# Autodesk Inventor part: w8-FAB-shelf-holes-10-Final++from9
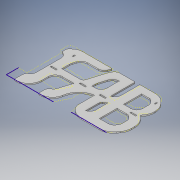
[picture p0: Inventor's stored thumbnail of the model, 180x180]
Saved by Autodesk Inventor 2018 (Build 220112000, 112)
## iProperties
Created: 2018-03
Part Number: w8-FAB-shelf-holes-10-Final++from9
Material: Generic
Document SubType Name: Modeling
Designer: katin
Density: 1 g/cm^3
Appearance: Default
Mass: 2764.59 g
Surface Area: 5789.53 cm^2
Volume: 2764.59 cm^3
Author: katin
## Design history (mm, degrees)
sketch "Sketch1"
  geometry: L1 (0, -103.188)-(-76.2, -103.188); L2 (-382.588, -407.987)-(-201.613, -407.987); L3 (-201.613, -407.987)-(-179.387, -330.2); L4 (-179.387, -330.2)-(-179.387, -303.315); L5 (-179.387, -303.315)-(-382.588, -303.315); L6 (-382.588, -303.315)-(-382.588, -330.2); L7 (-382.588, -330.2)-(-404.813, -407.987); L8 (-404.813, -407.987)-(-446.104, -500); L9 (-914.4, -410.18)-(-914.4, -330.2); L10 (-914.4, -330.2)-(-863.6, -279.4); L11 (-863.6, -279.4)-(-941.188, -201.812); L12 (-941.188, -100.013)-(-863.6, 0); L13 (-611.188, -500)-(-611.188, -274.637); L14 (-660.987, -274.638)-(-660.987, -501.799); L15 (-660.987, -203.2)-(-660.987, -104.775); L16 (-611.188, -104.775)-(-660.987, -104.775); L17 (-458.721, -302.879)-(-458.721, -330.2); L18 (-458.721, -330.2)-(-480.946, -407.987); L19 (-480.946, -407.987)-(-534.987, -407.987); L20 (-534.987, -407.987)-(-534.988, -302.879); L21 (-534.988, -302.879)-(-458.721, -302.879); L22 (-180.346, -201.117)-(-180.346, -104.775); L23 (-180.346, -104.775)-(-330, -104.775); L24 (-180.346, -201.117)-(-380.371, -201.117); L25 (-380.371, -201.117)-(-330, -104.775); L26 (-458.721, -201.117)-(-458.721, -104.775); L27 (-458.721, -201.117)-(-534.987, -201.117); L28 (-534.987, -201.117)-(-534.987, -104.775); L29 (-739.719, -407.987)-(-739.719, -306.388); L30 (-739.719, -407.987)-(-815.975, -407.987); L31 (-841.375, -354.012)-(-841.375, -381); L32 (-841.375, -381)-(-815.975, -407.987); L33 (-382.588, -407.987)-(-424.795, -502.08); L34 (-79.965, -502.08)-(-424.795, -502.08); L35 (-611.188, -104.775)-(-611.188, -203.2); L36 (-611.188, -500)-(-446.104, -500); L37 (0, -103.188)-(0, 0); L38 (-941.188, -201.812)-(-941.188, -100.013); L39 (0, -103.188)-(0, 0); L40 (0, 0)-(-406.4, 0); L41 (-406.4, 0)-(-458.721, -104.775); L42 (-534.987, -104.775)-(-558.8, 0); L43 (-611.188, -203.2)-(-660.987, -233.363); L44 (-660.987, -233.363)-(-660.987, -203.2); L45 (-558.8, 0)-(-863.6, 0); L46 (0, 0)-(-406.4, 0); L47 (-79.965, -502.08)-(-50.58, -485.849); L48 (-50.58, -485.849)-(-50.58, -407.987); L49 (-50.58, -407.987)-(-76.2, -407.987); L50 (-76.2, -407.987)-(-76.2, -103.188); L51 (-841.375, -354.012)-(-793.75, -306.388); L52 (-793.75, -306.388)-(-739.719, -306.388); L53 (-611.188, -274.637)-(-660.987, -274.638); L54 (-739.762, -201.612)-(-739.762, -103.187); L55 (-739.762, -103.187)-(-836.612, -103.188); L56 (-836.612, -103.188)-(-863.6, -138.112); L57 (-863.6, -138.112)-(-863.6, -176.213); L58 (-863.6, -176.213)-(-838.2, -201.612); L59 (-838.2, -201.612)-(-739.762, -201.612); L60 (-914.4, -410.18)-(-838.2, -501.799); L61 (-838.2, -501.799)-(-660.987, -501.799); L62 (0, 0)-(-406.4, 0); L63 (-558.8, 0)-(-863.6, 0)
  constraints: 126 end point, 13 perpendicular, 13 point on line, 10 vertical, 9 horizontal, 3 collinear, 1 parallel
sketch "Sketch2"
  geometry: L1 (0, 0)-(-940, 0); L2 (-940, 0)-(-940, -500); L3 (-940, -500)-(0, -500); L4 (0, -500)-(0, 0)
  constraints: 8 end point, 2 parallel, 1 horizontal, 1 perpendicular
  dimensions: "d10" = 940 distance of L3.end L2.end; "d11" = 500 distance of L2.end L1.end
extrude "Extrusion2" new body sketch "Sketch2" distance "d12" = 11; taper "d13" = 0 deg
sketch "Sketch3"
  geometry: L1 (0, 0)-(0, 500) reference; L2 (0, 408.758)-(113.674, 408.758); L3 (113.674, 408.758)-(113.674, 94.825); L4 (113.674, 94.825)-(0, 94.825); L5 (0, 94.825)-(0, 408.758); L6 (611.188, 500.062)-(650.182, 500.062); L7 (650.182, 500.062)-(650.182, 287.702); L8 (650.182, 287.702)-(611.188, 287.702); L9 (611.188, 287.702)-(611.188, 500.062); L10 (0, 500)-(129.919, 500); L11 (0, 500)-(940, 500) reference; L12 (129.919, 500)-(0, 408.758); L13 (0, 500)-(0, 408.758); L14 (739.775, 406.4)-(739.775, 307.975); L15 (739.775, 307.975)-(793.75, 307.975); L16 (793.75, 307.975)-(836.612, 350.838); L17 (836.612, 350.838)-(841.375, 355.6); L18 (841.375, 355.6)-(841.375, 381); L19 (841.375, 381)-(806.218, 418.355); L20 (806.218, 418.355)-(739.775, 418.355); L21 (739.775, 418.355)-(739.775, 406.4)
  constraints: 38 end point, 6 parallel, 4 perpendicular, 4 point on line, 2 horizontal, 1 collinear, 1 vertical
extrude "Extrusion3" cut sketch "Sketch3" distance "d14" = 150; taper "d15" = 0 deg
sketch "Sketch4"
  geometry: L1 (0, 500)-(940, 500) reference; L2 (839.788, 500)-(914.4, 411.163); L3 (914.4, 411.163)-(914.4, 310.193); L4 (914.4, 310.193)-(880.473, 275.82); L5 (880.473, 275.82)-(940, 217.064); L6 (940, 217.064)-(940, 500); L7 (940, 500)-(839.788, 500); L8 (940, 0)-(940, 500) reference; L9 (940, 99.14)-(940, 0); L10 (940, 0)-(863.6, 0); L11 (0, 0)-(940, 0) reference; L12 (940, 99.14)-(863.6, 0); L13 (728.744, 226.212)-(728.744, 72.721); L14 (728.744, 72.721)-(830.691, 72.721); L15 (830.691, 72.721)-(864.394, 116.456); L16 (864.394, 116.456)-(864.405, 192.017); L17 (864.405, 192.017)-(829.761, 226.212); L18 (829.761, 226.212)-(728.744, 226.212); L19 (649.575, 72.721)-(649.575, 226.081); L20 (649.575, 226.081)-(611.188, 202.869); L21 (611.188, 202.869)-(611.188, 72.721); L22 (611.188, 72.721)-(649.575, 72.721); L23 (727.378, 439.44)-(727.378, 283.141); L24 (727.378, 283.141)-(801.955, 283.141); L25 (801.955, 283.141)-(841.375, 322.561); L26 (841.375, 322.561)-(841.375, 403.65); L27 (841.375, 403.65)-(807.69, 439.44); L28 (807.69, 439.44)-(727.378, 439.44); L29 (534.987, 283.141)-(534.987, 439.44); L30 (534.987, 439.44)-(490.381, 439.44); L31 (490.381, 439.44)-(455.193, 321.307); L32 (455.193, 321.307)-(455.193, 283.141); L33 (455.193, 283.141)-(534.987, 283.141); L34 (534.987, 226.027)-(534.987, 72.721); L35 (534.987, 72.721)-(560.388, 0); L36 (560.388, 0)-(405.603, 0); L37 (455.193, 72.721)-(405.603, 0); L38 (455.193, 72.721)-(455.193, 226.027); L39 (455.193, 226.027)-(534.987, 226.027); L40 (250.031, 72.721)-(195.665, 72.721); L41 (195.665, 72.721)-(195.665, 226.027); L42 (195.665, 226.027)-(354.575, 226.027); L43 (354.575, 226.027)-(250.031, 72.721); L44 (195.665, 283.141)-(195.665, 362.436); L45 (195.665, 362.436)-(218.603, 439.44); L46 (218.603, 439.44)-(389.781, 439.44); L47 (389.781, 439.44)-(415.52, 500); L48 (415.52, 500)-(447.675, 500); L49 (611.188, 500)-(129.919, 500) reference; L50 (195.665, 283.141)-(380.412, 283.141); L51 (380.412, 283.141)-(380.412, 300.037); L52 (380.412, 300.037)-(421.936, 439.44); L53 (421.936, 439.44)-(447.675, 500); L54 (415.52, 500)-(447.675, 500); 1 further point
  constraints: 100 end point, 28 point on line, 12 perpendicular, 11 parallel, 3 vertical, 2 collinear
extrude "Extrusion4" cut sketch "Sketch4" distance "d16" = 150; taper "d17" = 0 deg
fillet "Fillet1" dims "d18" = 50
fillet "Fillet2" dims "d19" = 50
fillet "Fillet3" dims "d20" = 50
fillet "Fillet4" dims "d21" = 60
fillet "Fillet7" dims "d24" = 30
fillet "Fillet8" dims "d25" = 50
fillet "Fillet9" dims "d26" = 50
fillet "Fillet10" dims "d27" = 50
fillet "Fillet13" dims "d30" = 40
fillet "Fillet14" dims "d31" = 120
fillet "Fillet15" dims "d32" = 120
fillet "Fillet16" dims "d33" = 120
fillet "Fillet17" dims "d34" = 50
fillet "Fillet18" dims "d35" = 50
fillet "Fillet19" dims "d36" = 170
fillet "Fillet20" dims "d37" = 65
fillet "Fillet21" dims "d38" = 50
fillet "Fillet22" dims "d39" = 5
fillet "Fillet25" dims "d42" = 25
fillet "Fillet26" dims "d43" = 50
fillet "Fillet27" dims "d44" = 90
sketch "Sketch5"
  geometry: L1 (195.665, 72.721)-(195.665, 0); L2 (195.665, 0)-(278.632, 0); L3 (0, 0)-(285.193, 0) reference; L4 (278.632, 80.606)-(278.632, 0); L5 (278.632, 80.606)-(278.632, 104.775); L6 (223.608, 72.721)-(195.665, 72.721) reference; L7 (278.632, 104.775)-(195.665, 72.721)
  constraints: 10 end point, 2 vertical, 1 perpendicular, 1 point on line
extrude "Extrusion5" cut sketch "Sketch5" distance "d45" = 150; taper "d46" = 0 deg
sketch "Sketch6"
  geometry: L1 (463.037, 222.547)-(398.463, 127.297); L2 (398.463, 127.297)-(398.463, 22.263); L3 (455.193, 283.141)-(455.193, 311.832) reference; L4 (398.463, 22.263)-(534.988, 22.263); L5 (534.987, 226.027)-(534.987, 72.721) reference; L6 (534.988, 22.263)-(534.987, 226.027); L7 (534.987, 226.027)-(463.037, 222.547); 2 further points
  constraints: 10 end point, 2 perpendicular, 1 parallel
extrude "Extrusion6" cut sketch "Sketch6" distance "d48" = 150; taper "d49" = 0 deg
fillet "Fillet29" dims "d50" = 100
fillet "Fillet30" dims "d51" = 40
sketch "Sketch7"
  geometry: L1 (242.804, 83.41)-(242.804, 226.022); L2 (242.804, 226.022)-(357.713, 226.022); L3 (306.387, 83.41)-(242.804, 83.41); L4 (357.713, 226.022)-(313.861, 83.41); L5 (313.861, 83.41)-(242.804, 83.41); 1 further point
  constraints: 10 end point, 1 horizontal, 1 parallel, 1 perpendicular, 1 vertical
extrude "Extrusion7" cut sketch "Sketch7" distance "d52" = 150; taper "d53" = 0 deg
fillet "Fillet31" dims "d54" = 40
sketch "Sketch8"
  geometry: L1 (505.193, 226.027)-(534.987, 226.027) reference; L2 (534.987, 226.027)-(534.987, 72.721) reference; L3 (534.987, 127.541)-(534.987, 226.027); L4 (403.342, 127.541)-(534.987, 127.541); L5 (534.987, 226.027)-(435.488, 226.027); L6 (435.488, 226.027)-(403.342, 127.541); A1 r 100 centre (498.406, 96.512) between (415.634, 152.627) and (398.434, 98.891) reference; A2 r 100 centre (498.406, 96.512) between (415.634, 152.627) and (398.434, 98.891) reference; 2 further points
  constraints: 8 end point, 2 horizontal, 1 point on circle, 1 point on line, 1 tangent, 1 vertical
extrude "Extrusion8" cut sketch "Sketch8" distance "d55" = 150; taper "d56" = 0 deg
fillet "Fillet32" dims "d57" = 160
sketch "Sketch9"
  geometry: L1 (841.375, 322.561)-(801.955, 283.141) reference; L2 (841.375, 322.561)-(841.375, 298.749); L3 (841.375, 298.749)-(842.323, 283.141); L4 (842.323, 283.141)-(801.955, 283.141); 1 further point
  constraints: 6 end point, 1 perpendicular, 1 vertical
extrude "Extrusion9" cut sketch "Sketch9" distance "d58" = 150; taper "d59" = 0 deg
fillet "Fillet33" dims "d60" = 50
fillet "Fillet34" dims "d61" = 110
fillet "Fillet43" dims "d70" = 50
fillet "Fillet44" dims "d71" = 5
fillet "Fillet45" dims "d72" = 40
sketch "Sketch10"
  geometry: L1 (-1.587, 508)-(69.85, 508); L2 (69.85, 508)-(69.85, -22.225); L3 (69.85, -22.225)-(-1.587, -22.225); L4 (-1.587, -22.225)-(-1.587, 508); 1 further point
  constraints: 8 end point, 2 parallel, 1 horizontal, 1 perpendicular
extrude "Extrusion10" cut sketch "Sketch10" distance "d73" = 150; taper "d74" = 0 deg
fillet "Fillet46" dims "d75" = 40
fillet "Fillet47" dims "d76" = 5
fillet "Fillet48" dims "d77" = 5
fillet "Fillet49" dims "d78" = 5
sketch "Sketch12"
  geometry: C1 r 5 at (151.971, -436.562); C2 r 5 at (858.837, -436.562); 1 further point
  constraints: 2 centre point
  dimensions: "d85" = 10 diameter of C1; "d86" = 10 diameter of C2
extrude "Extrusion11" cut sketch "Sketch12" distance "d89" = 12; taper "d90" = 0 deg
sketch "Sketch16"
  geometry: L1 (131.762, 258.023)-(181.762, 258.023); L2 (181.762, 258.023)-(181.762, 247.023); L3 (181.762, 247.023)-(131.762, 247.023); L4 (131.762, 247.023)-(131.762, 258.023); L5 (382.587, 258.023)-(432.587, 258.023); L6 (432.587, 258.023)-(432.587, 247.023); L7 (432.587, 247.023)-(382.587, 247.023); L8 (382.587, 247.023)-(382.587, 258.023); L9 (554.038, 258.023)-(604.038, 258.023); L10 (604.038, 258.023)-(604.038, 247.023); L11 (604.038, 247.023)-(554.038, 247.023); L12 (554.038, 247.023)-(554.038, 258.023); L13 (817.562, 258.023)-(867.562, 258.023); L14 (867.562, 258.023)-(867.562, 247.023); L15 (867.562, 247.023)-(817.562, 247.023); L16 (817.562, 247.023)-(817.562, 258.023); 1 further point
  constraints: 32 end point, 8 parallel, 4 horizontal, 4 perpendicular, 2 point on line
  dimensions: "d106" = 50 distance of L2.end L3.end; "d107" = 11 distance of L1.end L2.end; "d108" = 50 distance of L6.end L7.end; "d109" = 11 distance of L5.end L6.end; "d110" = 50 distance of L10.end L11.end; "d111" = 11 distance of L9.end L10.end; "d112" = 50 distance of L14.end L15.end; "d113" = 11 distance of L13.end L14.end
extrude "Extrusion15" cut sketch "Sketch16" distance "d114" = 110; taper "d115" = 0 deg
sketch "Sketch26"
  geometry: L1 (152.028, -436.437)-(152.028, -423.808); L2 (156.328, -436.437)-(156.328, -423.808); L3 (147.728, -423.808)-(147.728, -436.437); L4 (858.846, -436.437)-(858.846, -423.808); L5 (863.146, -436.437)-(863.146, -423.808); L6 (854.546, -423.808)-(854.546, -436.437); A1 r 4.3 centre (152.028, -436.437) between (147.728, -436.437) and (156.328, -436.437); A2 r 4.3 centre (152.028, -423.808) between (156.328, -423.808) and (147.728, -423.808); A3 r 4.3 centre (858.846, -436.437) between (854.546, -436.437) and (863.146, -436.437); A4 r 4.3 centre (858.846, -423.808) between (863.146, -423.808) and (854.546, -423.808); 3 further points
  constraints: 16 end point, 8 point on circle, 8 tangent, 4 centre point, 2 midpoint, 2 parallel, 2 vertical
  dimensions: "d163" = 8.6 diameter of A2; "d164" = 8.6 diameter of A4
extrude "Extrusion24" cut sketch "Sketch26" distance "d165" = 12; taper "d166" = 0 deg
body "Solid2"
